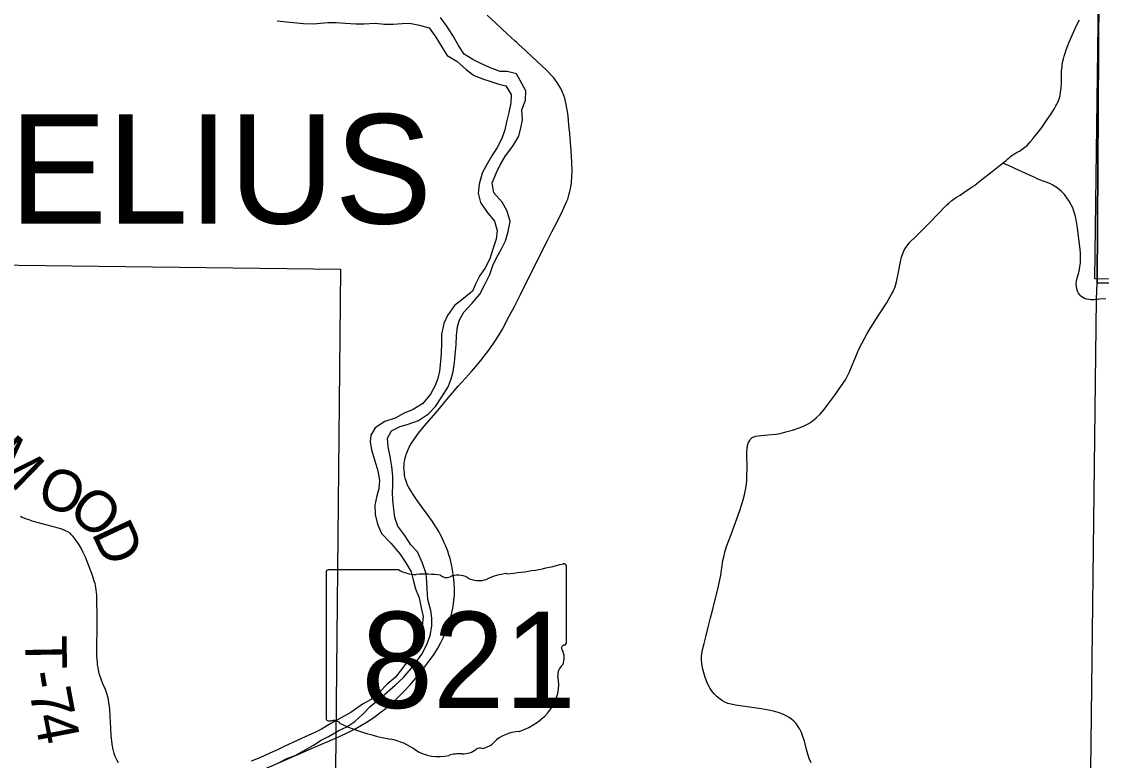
# Model space of a CAD drawing. Extents: x 0 to 34, y 0 to 22.
# Drawn here: x 2.925 to 4.406, y 16.759 to 17.772 of the extents above; entities that cross this region are included whole.
import ezdxf

# ---------------------------------------------------------------- set-up
doc = ezdxf.new("R2010")
doc.units = 0
for name, color, linetype in [('GM_X_Corporation', 7, 'Continuous'), ('GM_X_Major_River', 7, 'Continuous'), ('GM_X_State_Location', 7, 'Continuous'), ('GM_X_State_Route', 7, 'Continuous'), ('GM_X_State_Shield', 7, 'Continuous'), ('GM_X_Township_Road', 7, 'Continuous'), ('GM_X_Township_Road_Text', 7, 'Continuous'), ('GM_X_Township_Text', 7, 'Continuous')]:
    doc.layers.add(name, color=color, linetype=linetype)

msp = doc.modelspace()

# ---------------------------------------------------------------- linework, layer by layer
at = {"layer": 'GM_X_Corporation'}
msp.add_lwpolyline([(4.6584, 17.4085), (4.4004, 17.4134), (4.4034, 17.9703), (4.4042, 18.3894), (4.0024, 18.3976), (3.4726, 18.3965), (3.3689, 18.3973), (3.3767, 18.6788), (3.3859, 18.705), (3.3893, 18.721), (3.3872, 18.7823), (3.3779, 18.9241), (3.3711, 18.9531), (3.3709, 19.4088), (3.3147, 19.4093), (2.7824, 19.4152), (2.1, 19.4241), (2.1, 14.1)], dxfattribs=at)
for points in [[(4.4097, 18.3961), (5.4623, 18.3997), (5.4343, 17.4017), (4.3969, 17.419)], [(2.3314, 17.4451), (3.3626, 17.4322), (3.3525, 16.4245), (2.3088, 16.4308)]]:
    msp.add_lwpolyline(points, close=True, dxfattribs=at)
at = {"layer": 'GM_X_Major_River'}
for points in [[(3.2757, 17.7726), (3.2886, 17.7713), (3.2981, 17.7707), (3.3118, 17.7693), (3.3251, 17.7688), (3.3349, 17.7696), (3.3451, 17.7705), (3.3565, 17.7703), (3.369, 17.7697), (3.3834, 17.7688), (3.3948, 17.7686), (3.41, 17.7695)], [(3.2786, 16.7555), (3.2891, 16.761), (3.3004, 16.7653), (3.3117, 16.7715), (3.3256, 16.7797), (3.3358, 16.7862), (3.3459, 16.7913), (3.3602, 16.7995), (3.3712, 16.8045), (3.3821, 16.8119), (3.394, 16.8227), (3.403, 16.8323), (3.4158, 16.8431), (3.4266, 16.8523), (3.4375, 16.862), (3.4487, 16.8723), (3.4592, 16.8842), (3.4674, 16.8946), (3.4741, 16.9042), (3.4807, 16.9175), (3.4855, 16.9297), (3.4876, 16.9427), (3.4878, 16.9537), (3.4865, 16.9643), (3.4821, 16.9794), (3.4812, 16.9938), (3.4807, 17.0036), (3.4801, 17.0146), (3.475, 17.0293), (3.468, 17.0444), (3.4588, 17.0542), (3.4506, 17.0669), (3.441, 17.0797), (3.437, 17.0918), (3.4357, 17.1031), (3.4344, 17.116), (3.4339, 17.1255), (3.4345, 17.135), (3.4343, 17.1486), (3.433, 17.1615), (3.4306, 17.1755), (3.4277, 17.1887), (3.4272, 17.2005), (3.4324, 17.2104), (3.4444, 17.2167), (3.4554, 17.2198), (3.4693, 17.2246), (3.4832, 17.2339), (3.493, 17.2439), (3.5026, 17.2584), (3.51, 17.271), (3.5144, 17.2817), (3.5169, 17.292), (3.519, 17.3041), (3.52, 17.3148), (3.521, 17.3284), (3.5216, 17.3413), (3.5229, 17.3531), (3.5258, 17.3626), (3.5318, 17.3733), (3.5433, 17.3856), (3.5538, 17.3979), (3.5604, 17.4113), (3.5671, 17.425), (3.5715, 17.4372), (3.5766, 17.4479), (3.5833, 17.4601), (3.5888, 17.4712), (3.5924, 17.4838), (3.5953, 17.4978), (3.5913, 17.5118), (3.5843, 17.5242), (3.5727, 17.537), (3.5703, 17.5506), (3.5765, 17.5647), (3.5817, 17.5754), (3.5887, 17.5876), (3.5988, 17.601), (3.6069, 17.6148), (3.6102, 17.6277), (3.6119, 17.6372), (3.611, 17.6509), (3.6161, 17.6638), (3.6167, 17.6768), (3.6113, 17.6869), (3.6039, 17.7001), (3.591, 17.7033), (3.5815, 17.7032), (3.567, 17.7087), (3.554, 17.7146), (3.5441, 17.7198), (3.5319, 17.7272), (3.5245, 17.7392), (3.5164, 17.7528), (3.5082, 17.7655), (3.4997, 17.7776)], [(3.41, 17.7695), (3.4229, 17.7682), (3.4346, 17.7683), (3.4471, 17.7693), (3.457, 17.7694), (3.471, 17.7669), (3.484, 17.7633), (3.4933, 17.7506), (3.5018, 17.7363), (3.5088, 17.7254), (3.5221, 17.7176), (3.5348, 17.706), (3.5448, 17.6985), (3.5574, 17.6934), (3.5673, 17.6901), (3.5798, 17.6861), (3.5893, 17.6836), (3.5967, 17.6716), (3.5961, 17.6602), (3.5936, 17.6469), (3.59, 17.6343), (3.5879, 17.6233), (3.5839, 17.6115), (3.5776, 17.5989), (3.5702, 17.5878), (3.5631, 17.5759), (3.5568, 17.5641), (3.5529, 17.5488), (3.5515, 17.5367), (3.5547, 17.5238), (3.5632, 17.5107), (3.5737, 17.4983), (3.5776, 17.4851), (3.5759, 17.4733), (3.5715, 17.4596), (3.5672, 17.4466), (3.5605, 17.4333), (3.5534, 17.4237), (3.5475, 17.4115), (3.5435, 17.4019), (3.5289, 17.3904), (3.5187, 17.3826), (3.5091, 17.3689), (3.5043, 17.3578), (3.5011, 17.343), (3.5012, 17.3304), (3.5007, 17.3172), (3.4997, 17.3058), (3.4984, 17.2925), (3.4958, 17.2822), (3.4922, 17.2727), (3.4859, 17.2608), (3.4755, 17.2482), (3.4623, 17.24), (3.4499, 17.2346), (3.4374, 17.2279), (3.4235, 17.2232), (3.4099, 17.2147), (3.404, 17.2047), (3.4034, 17.1949), (3.405, 17.1846), (3.4098, 17.1692), (3.4138, 17.1556), (3.4162, 17.1423), (3.4149, 17.1309), (3.4123, 17.1214), (3.4095, 17.1085), (3.41, 17.096), (3.4133, 17.0824), (3.4187, 17.0699), (3.4314, 17.0564), (3.4438, 17.0418), (3.4519, 17.0294), (3.4593, 17.017), (3.4621, 17.006), (3.4656, 16.9939), (3.4704, 16.9815), (3.4732, 16.9679), (3.476, 16.9558), (3.4743, 16.9432), (3.4688, 16.9306), (3.4625, 16.9165), (3.4567, 16.9013), (3.4522, 16.8917), (3.4462, 16.8834), (3.4374, 16.8724), (3.4264, 16.8632), (3.4161, 16.8522), (3.4048, 16.8422), (3.3927, 16.8356), (3.3766, 16.8243), (3.3627, 16.8166), (3.3495, 16.8092), (3.3363, 16.8014), (3.3265, 16.7964), (3.3149, 16.7913), (3.302, 16.7854), (3.2862, 16.778), (3.2761, 16.7729), (3.2655, 16.7686), (3.2519, 16.762)], [(3.2519, 16.762), (3.2402, 16.7576)]]:
    msp.add_lwpolyline(points, dxfattribs=at)
at = {"layer": 'GM_X_State_Route'}
for points in [[(3.6094, 17.7381), (3.606, 17.7413), (3.6042, 17.7429), (3.6014, 17.7454), (3.5914, 17.7547), (3.5756, 17.7696), (3.5637, 17.7805)], [(3.2548, 16.745), (3.2895, 16.7602), (3.3259, 16.7761), (3.3613, 16.7914), (3.3737, 16.7972), (3.3837, 16.8023), (3.3913, 16.8067), (3.3993, 16.8116), (3.4081, 16.8175), (3.4166, 16.8237), (3.425, 16.8303), (3.4335, 16.8376), (3.4417, 16.8452), (3.4496, 16.8532), (3.458, 16.8624), (3.4673, 16.8733), (3.4763, 16.8845), (3.4846, 16.8954), (3.491, 16.9045), (3.496, 16.9125), (3.5003, 16.9201), (3.5039, 16.9274), (3.5071, 16.9348), (3.5102, 16.943), (3.5129, 16.952), (3.5152, 16.9611), (3.5169, 16.9696), (3.518, 16.9777), (3.5187, 16.9858), (3.5188, 16.9939), (3.5185, 17.0021), (3.5177, 17.0108), (3.5163, 17.02), (3.5148, 17.0274), (3.5128, 17.0353), (3.5112, 17.0407), (3.5096, 17.0454), (3.5069, 17.0524), (3.5049, 17.0569), (3.5013, 17.0649), (3.4993, 17.0688), (3.4972, 17.0726), (3.4944, 17.0774), (3.4902, 17.084), (3.4889, 17.086), (3.485, 17.0914), (3.4752, 17.1048), (3.4668, 17.1163), (3.4614, 17.1246), (3.4593, 17.128), (3.4573, 17.1313), (3.4564, 17.133), (3.4554, 17.1346), (3.4546, 17.1362), (3.4539, 17.1379), (3.4529, 17.1401), (3.452, 17.1429), (3.4513, 17.1452), (3.4508, 17.1479), (3.4505, 17.1502), (3.4502, 17.1528), (3.4498, 17.1572), (3.4496, 17.1599), (3.4497, 17.1625), (3.4499, 17.1658), (3.4502, 17.1686), (3.4506, 17.1712), (3.4512, 17.1737), (3.4519, 17.1761), (3.4525, 17.1781), (3.4534, 17.1806), (3.4542, 17.1827), (3.4568, 17.1883), (3.4599, 17.1936), (3.464, 17.1998), (3.4695, 17.2072), (3.4773, 17.2169), (3.4935, 17.2357), (3.5108, 17.2561), (3.5241, 17.2716), (3.5341, 17.283), (3.5424, 17.2919), (3.5481, 17.2988), (3.5527, 17.3043), (3.5567, 17.3093), (3.5606, 17.3141), (3.5647, 17.3192), (3.568, 17.3238), (3.5715, 17.329), (3.5744, 17.3331), (3.5793, 17.341), (3.5846, 17.3502), (3.5939, 17.3677), (3.6014, 17.382), (3.6093, 17.3975), (3.6352, 17.4492), (3.6467, 17.4725), (3.6524, 17.4836), (3.6599, 17.4979), (3.6673, 17.513), (3.6713, 17.5215), (3.6726, 17.5247), (3.6741, 17.5284), (3.6752, 17.5318), (3.6763, 17.5356), (3.6771, 17.5388), (3.6778, 17.5424), (3.6785, 17.5458), (3.6791, 17.5499), (3.6794, 17.5532), (3.6797, 17.5573), (3.68, 17.5614), (3.6801, 17.5654), (3.6801, 17.5701), (3.68, 17.5747), (3.6798, 17.58), (3.6795, 17.5859), (3.6788, 17.595), (3.6779, 17.6057), (3.6769, 17.6181), (3.6757, 17.6298), (3.6752, 17.6361), (3.6746, 17.6422), (3.6738, 17.6484), (3.6731, 17.6532), (3.6722, 17.6581), (3.6712, 17.6624), (3.6701, 17.6666), (3.6689, 17.6702), (3.6667, 17.676), (3.6647, 17.68), (3.6625, 17.6838), (3.6598, 17.6881), (3.6569, 17.6921), (3.6549, 17.6945), (3.6533, 17.6964), (3.6516, 17.6983), (3.647, 17.7033), (3.6443, 17.7059), (3.6393, 17.7106), (3.6316, 17.7177), (3.6101, 17.7375), (3.6094, 17.7381)]]:
    msp.add_lwpolyline(points, dxfattribs=at)
at = {"layer": 'GM_X_State_Shield'}
for p, q in [((3.3427, 17.0165), (3.3427, 16.8164)), ((3.4424, 17.02), (3.3459, 17.02)), ((3.6723, 16.9203), (3.6723, 17.0249)), ((3.6722, 16.9203), (3.6723, 16.9203))]:
    msp.add_line(p, q, dxfattribs=at)
for centre, major_axis, start_param, end_param in [((3.3465, 17.017), (0.00382, 0), 1.712693, 3.28349), ((3.4654, 17.0432), (0.037, 0), 4.042523, 4.731795), ((3.5994, 16.9589), (0.0703, 0), 1.699011, 2.107814), ((3.5549, 17.2928), (0.3495, 0), 4.814394, 5.042369), ((3.6686, 17.0254), (0.00367, 0), 6.141152, 7.989035), ((3.4777, 16.9076), (0.133, 0), 1.404758, 1.657858), ((3.5079, 17.018), (0.0107, 0), 3.836095, 5.185415), ((3.5236, 16.9949), (0.0222, 0), 0.950623, 2.079405), ((3.5523, 17.0266), (0.0267, 0), 4.081561, 5.145723), ((3.6714, 16.9126), (0.00568, 0), 1.883978, 3.671073), ((3.6684, 16.9198), (0.00393, 0), 5.05454, 6.418171), ((3.6353, 16.8993), (0.0341, 0), 5.934695, 6.695948), ((3.6854, 16.8764), (0.0248, 0), 2.387724, 3.262537), ((3.5744, 16.8631), (0.0874, 0), 5.101752, 6.440018), ((3.3465, 16.816), (0.00385, 0), 3.00124, 4.508301), ((3.3471, 16.8365), (0.0294, 0), 4.665946, 4.897461), ((3.3531, 16.8049), (0.0106, 0), 0.519207, 1.627899), ((3.4869, 16.9847), (0.2524, 0), 4.195997, 4.488961), ((3.6113, 16.7602), (0.0479, 0), 1.647645, 2.488434), ((3.4117, 16.7265), (0.079, 0), 0.823519, 1.323587), ((3.5506, 16.797), (0.0282, 0), 4.937069, 5.64225), ((3.4971, 16.8039), (0.0501, 0), 4.026481, 4.996735), ((3.526, 16.7347), (0.0412, 0), 1.495662, 1.94098), ((3.5297, 16.7889), (0.0267, 0), 4.691044, 5.507374), ((3.5538, 16.7695), (0.00752, 0), 1.147584, 2.315152)]:
    msp.add_ellipse(centre, major_axis=major_axis, ratio=0.8, start_param=start_param, end_param=end_param, dxfattribs=at)
at = {"layer": 'GM_X_Township_Road'}
for points in [[(4.2707, 17.5777), (4.2724, 17.5791), (4.2752, 17.5815), (4.2778, 17.5837), (4.2799, 17.5854), (4.2813, 17.5866), (4.2833, 17.5881), (4.2845, 17.589), (4.2857, 17.5898), (4.2872, 17.5907), (4.2892, 17.5918), (4.2915, 17.5931), (4.2936, 17.5943), (4.2954, 17.5953), (4.2975, 17.5967), (4.2994, 17.5982), (4.301, 17.5994), (4.3028, 17.6009), (4.3045, 17.6025), (4.3063, 17.6044), (4.3085, 17.6069), (4.312, 17.611), (4.3149, 17.6145), (4.3174, 17.6178), (4.321, 17.6223), (4.3242, 17.6267), (4.3279, 17.6319), (4.3316, 17.6374), (4.336, 17.6438), (4.3402, 17.6503), (4.342, 17.6533), (4.3436, 17.6562), (4.345, 17.6586), (4.3461, 17.6612), (4.3479, 17.6659), (4.3493, 17.6706), (4.3501, 17.6749), (4.3507, 17.6798), (4.3511, 17.6892), (4.3515, 17.704), (4.352, 17.7103), (4.3523, 17.7128), (4.3527, 17.7153), (4.3532, 17.7175), (4.3539, 17.7206), (4.355, 17.7243), (4.3563, 17.7284), (4.3578, 17.7332), (4.3599, 17.7389), (4.3613, 17.7427), (4.363, 17.7469), (4.3657, 17.7531), (4.3682, 17.7584), (4.3723, 17.7671), (4.3758, 17.774)], [(4.0078, 16.7554), (4.0053, 16.7611), (4.0033, 16.767), (4.0015, 16.7736), (3.9987, 16.7851), (3.9967, 16.7916), (3.9947, 16.7968), (3.9925, 16.8013), (3.9899, 16.8055), (3.9873, 16.809), (3.9843, 16.8122), (3.9811, 16.8151), (3.9776, 16.8176), (3.9738, 16.8198), (3.9693, 16.8219), (3.9641, 16.8239), (3.9581, 16.8257), (3.9497, 16.8276), (3.9393, 16.8294), (3.9233, 16.8317), (3.9042, 16.8345), (3.8982, 16.8355), (3.8935, 16.8367), (3.8897, 16.8384), (3.8866, 16.8402), (3.883, 16.8427), (3.8792, 16.8458), (3.8756, 16.8493), (3.8724, 16.8531), (3.8695, 16.8571), (3.8671, 16.8614), (3.8647, 16.8665), (3.8626, 16.8723), (3.8606, 16.8788), (3.8591, 16.8854), (3.8582, 16.8914), (3.8577, 16.8969), (3.8577, 16.9012), (3.8582, 16.9054), (3.8595, 16.912), (3.8612, 16.9191), (3.864, 16.9298), (3.8669, 16.9412), (3.87, 16.9539), (3.873, 16.9659), (3.8754, 16.9756), (3.88, 16.9936), (3.8825, 17.0038), (3.884, 17.0124), (3.887, 17.0327), (3.888, 17.0376), (3.8896, 17.0442), (3.8921, 17.0519), (3.8982, 17.0682), (3.9062, 17.0897), (3.9102, 17.1015), (3.9147, 17.1157), (3.9167, 17.1228), (3.9181, 17.1295), (3.9192, 17.1375), (3.9196, 17.1425), (3.9197, 17.1456), (3.9199, 17.1499), (3.9201, 17.1586), (3.9198, 17.1802), (3.9198, 17.1828), (3.92, 17.1851), (3.9201, 17.1862), (3.9202, 17.1873), (3.9205, 17.1888), (3.9208, 17.1903), (3.9212, 17.1918), (3.9217, 17.1933), (3.9222, 17.1946), (3.923, 17.196), (3.9238, 17.1974), (3.9245, 17.1985), (3.9254, 17.1996), (3.9263, 17.2004), (3.9272, 17.2012), (3.9283, 17.2018), (3.9294, 17.2024), (3.9306, 17.2028), (3.9321, 17.2032), (3.9352, 17.2038), (3.9395, 17.2043), (3.9487, 17.2051), (3.9593, 17.2061), (3.9654, 17.2071), (3.9732, 17.209), (3.9822, 17.2116), (3.9928, 17.215), (3.9986, 17.2173), (4.003, 17.2196), (4.0073, 17.2222), (4.0117, 17.2255), (4.0155, 17.2288), (4.0203, 17.2336), (4.0256, 17.2397), (4.031, 17.2466), (4.0404, 17.2596), (4.0498, 17.2728), (4.0549, 17.2806), (4.058, 17.2859), (4.0607, 17.2915), (4.0635, 17.2983), (4.0682, 17.3104), (4.0716, 17.3182), (4.0731, 17.3216), (4.0775, 17.3304), (4.0849, 17.3439), (4.0898, 17.3524), (4.0928, 17.3571), (4.0968, 17.3633), (4.1111, 17.3858), (4.1179, 17.397), (4.1201, 17.4007), (4.123, 17.4082), (4.1249, 17.4148), (4.1277, 17.4282), (4.1303, 17.4422), (4.1319, 17.4488), (4.1335, 17.4536), (4.1355, 17.4581), (4.1377, 17.4619), (4.1395, 17.4644), (4.141, 17.4663), (4.1435, 17.4691), (4.1504, 17.4761), (4.1605, 17.4863), (4.1719, 17.4977), (4.1793, 17.5052), (4.1836, 17.5097), (4.19, 17.5164), (4.194, 17.5204), (4.1967, 17.5229), (4.201, 17.5263), (4.2061, 17.5299), (4.2121, 17.5337), (4.2175, 17.5373), (4.2247, 17.5422), (4.2288, 17.545), (4.2318, 17.5472), (4.2353, 17.5498), (4.2421, 17.5551), (4.2562, 17.5662), (4.2655, 17.5735), (4.2688, 17.5762), (4.2707, 17.5777)], [(4.4005, 17.3907), (4.3996, 17.3906), (4.3955, 17.3902), (4.3917, 17.3902), (4.3887, 17.3905), (4.3856, 17.3911), (4.3827, 17.3922), (4.3805, 17.3933), (4.378, 17.3952), (4.3763, 17.397), (4.3745, 17.3995), (4.3732, 17.4023), (4.3723, 17.4052), (4.3717, 17.4089), (4.3716, 17.412), (4.3719, 17.4157), (4.3728, 17.4199), (4.3753, 17.4295), (4.3765, 17.4356), (4.3772, 17.4411), (4.3775, 17.4473), (4.3773, 17.4547), (4.3765, 17.4633), (4.3748, 17.4774), (4.373, 17.4891), (4.3713, 17.5001), (4.37, 17.5062), (4.3684, 17.5116), (4.3666, 17.5162), (4.3646, 17.5207), (4.3618, 17.5256), (4.3587, 17.5302), (4.3552, 17.5346), (4.3514, 17.5387), (4.3477, 17.542), (4.3458, 17.5435), (4.3438, 17.5449), (4.3396, 17.5475), (4.3352, 17.5497), (4.3289, 17.5522), (4.3213, 17.5549), (4.3179, 17.5563), (4.3145, 17.5578), (4.3081, 17.5608), (4.3013, 17.564), (4.2934, 17.5675), (4.2784, 17.5743), (4.2707, 17.5777)], [(4.4122, 17.3914), (4.4035, 17.3909), (4.4005, 17.3907)], [(3.0582, 16.7553), (3.0558, 16.7596), (3.0537, 16.7641), (3.0522, 16.7682), (3.0509, 16.7737), (3.0496, 16.781), (3.0482, 16.7927), (3.0474, 16.8026), (3.0467, 16.8193), (3.0461, 16.8292), (3.045, 16.8378), (3.0437, 16.8445), (3.0421, 16.8504), (3.0402, 16.8557), (3.0368, 16.8636), (3.0342, 16.8699), (3.0324, 16.8752), (3.0316, 16.8779), (3.031, 16.8805), (3.0305, 16.8828), (3.03, 16.886), (3.0295, 16.8895), (3.0291, 16.8934), (3.0287, 16.8976), (3.0285, 16.9015), (3.0284, 16.9072), (3.0283, 16.9133), (3.0288, 16.9418), (3.0289, 16.9598), (3.0286, 16.9754), (3.0282, 16.9853), (3.028, 16.9888), (3.0275, 16.9927), (3.027, 16.9956), (3.0265, 16.9983), (3.0259, 17.001), (3.0249, 17.0043), (3.0219, 17.0137), (3.0176, 17.0254), (3.0127, 17.0375), (3.0094, 17.0448), (3.0068, 17.0497), (3.0026, 17.0566), (2.9988, 17.0622), (2.996, 17.0656), (2.9937, 17.068), (2.9916, 17.0701), (2.9887, 17.072), (2.9855, 17.0735), (2.9818, 17.0751), (2.9773, 17.0767), (2.9739, 17.0777), (2.9707, 17.0785), (2.9673, 17.0795), (2.9638, 17.0804), (2.9586, 17.0817), (2.9484, 17.0844), (2.9395, 17.0869), (2.9354, 17.0883), (2.9318, 17.0895), (2.9288, 17.0906), (2.9261, 17.0919), (2.9238, 17.0929)]]:
    msp.add_lwpolyline(points, dxfattribs=at)
at = {"layer": 'GM_X_Township_Text'}
for points in [[(2.1, 19.4241), (2.7824, 19.4152), (3.3147, 19.4093), (3.3709, 19.4088), (3.3711, 18.9531), (3.3779, 18.9241), (3.3872, 18.7823), (3.3893, 18.721), (3.3859, 18.705), (3.3767, 18.6788), (3.3689, 18.3973), (3.4726, 18.3965), (4.0024, 18.3976), (4.4042, 18.3894), (4.4034, 17.9703), (4.4004, 17.4134), (4.6584, 17.4085)], [(2.1, 19.4241), (2.1, 16.074), (2.3294, 16.0685), (2.5414, 16.0663), (3.0911, 16.0497), (3.9428, 16.0275), (4.0565, 16.0246), (4.383, 16.0223), (4.3994, 17.3911), (4.4004, 17.4134)]]:
    msp.add_lwpolyline(points, dxfattribs=at)

# ---------------------------------------------------------------- texts
at = {"layer": 'GM_X_State_Location'}
for s in ['s', 'r']:
    msp.add_text(s, height=0.000189, dxfattribs=at).set_placement((3.5038, 16.9032))
msp.add_text('821', height=0.000189, rotation=0, dxfattribs=at).set_placement((3.4369, 16.8894))
at = {"layer": 'GM_X_State_Shield'}
msp.add_text('821', height=0.13184, dxfattribs=at).set_placement((3.3912, 16.8305))
at = {"layer": 'GM_X_Township_Road_Text'}
for s, rotation, p in [('M', 315.7458, (2.8762, 17.1684)), ('O', 341.4323, (2.9439, 17.1109)), ('O', 319.4864, (2.9864, 17.0978)), ('D', 295.0563, (3.0205, 17.0704)), ('T', 270.9901, (2.93, 16.9297)), ('-', 279.2557, (2.9315, 16.8783)), ('7', 280.7533, (2.9355, 16.8537)), ('4', 280.9802, (2.9421, 16.819))]:
    msp.add_text(s, height=0.0568, rotation=rotation, dxfattribs=at).set_placement(p)
at = {"layer": 'GM_X_Township_Text'}
msp.add_text('AURELIUS', height=0.15, rotation=0, dxfattribs=at).set_placement((2.485, 17.4948))

doc.saveas('drawing.dxf')
